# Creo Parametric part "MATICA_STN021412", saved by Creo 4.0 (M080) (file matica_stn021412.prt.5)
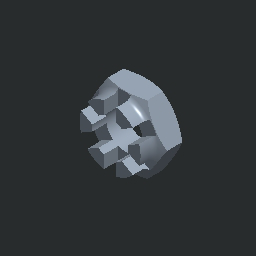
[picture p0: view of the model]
Units: millimeter Kilogram Sec (mmKs); MM, KILOGRAM, SECS
Materials in the file: OCEL_N

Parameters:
  MFG_WP_MATERIAL = "OCEL"
  NAZOV = "MATICA_STN021412"
  NORMA = "STN 02 1412"
  PTC_MATERIAL_NAME = "OCEL_N"

Other parameters: P, HMOTNOST, HUSTOTA, D66, D32, D64, D33, D62

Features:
  1. datum plane "DTM1"
  2. cut
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
Other named items: THRU

Layers: 1, 2, 3, 4, 5, 6, 7, 8, 9, 10, 11, 12, 13, 14, 15, 16, 17, 18, 19, 20, 21, 22, 23, 24, 25, 26, 27, 28, 29, 30, 31, 32

Family table entries: GENERIC, MATICA_M6, MATICA_STN021412, value(d_val), 2/$, value(i_val), !/1, !/N, 2/N, MATICA_M8, MATICA_STN021412, !/ , 2/*, !/1, !/N, 2/N, MATICA_M8X1, MATICA_STN021412, !/ , 2/*, !/1, !/N, 2/N, MATICA_M10, MATICA_STN021412, !/$, 2/ , 2/0, !/1, !/N, 2/N, MATICA_M10X1_25, MATICA_STN021412, !/$, 2/ , 2/0, !/1, !/N, 2/N, MATICA_M12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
